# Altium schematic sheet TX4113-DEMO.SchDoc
size A3; Author: 周跃鸿; CompanyName: 深圳市芯鼎盛技术有限公司; SheetNumber: A
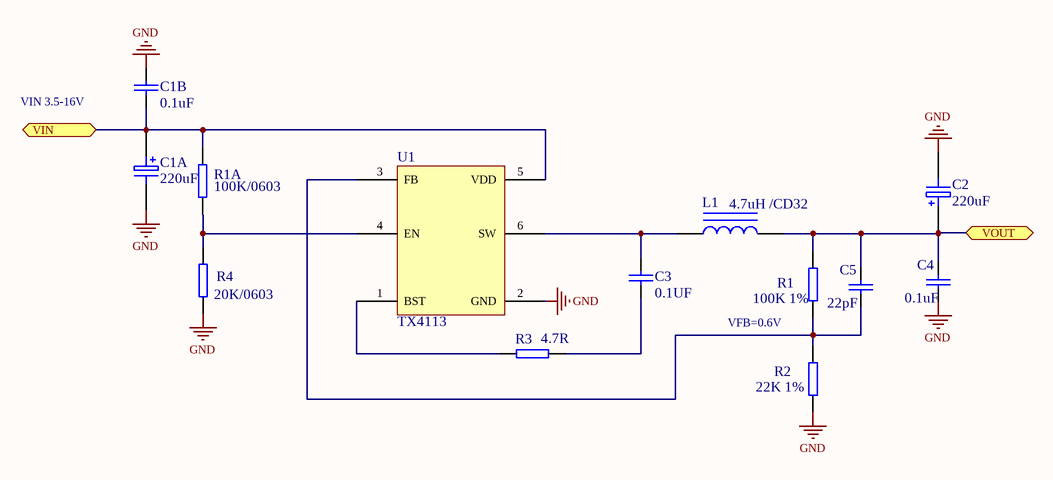
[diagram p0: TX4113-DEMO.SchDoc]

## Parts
C1A  220uF  [C10*16]
C1B  0.1uF  [C0805]
C2  220uF  [C10*16]
C3  0.1UF  [C0805]
C4  0.1uF  [C0805]
C5  22pF  [C0805]
L1  4.7uH /CD32  [L3015]
R1  100K 1%  [R0402]
R1A  100K/0603  [R0402]
R2  22K 1%  [R0402]
R3  4.7R  [R0402]
R4  20K/0603  [R0402]
U1  TX4113  [SOT23-6]

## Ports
VIN, VOUT (bidir)

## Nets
GND: C1A.2 C1B.1 C2.2 C4.2 R2.1 R4.1 U1.2(GND)
VIN: C1A.1 C1B.2 R1A.2 U1.5(VDD) ; port VIN
VOUT: C2.1 C4.1 C5.1 L1.2 R1.2 ; port VOUT
NetC3_1: C3.1 R3.1
NetC3_2: C3.2 L1.1 U1.6(SW)
NetC5_2: C5.2 R1.1 R2.2 U1.3(FB)
NetR1A_1: R1A.1 R4.2 U1.4(EN)
NetR3_2: R3.2 U1.1(BST)

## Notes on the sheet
- VIN 3.5-16V
- VFB=0.6V

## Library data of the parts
C1A C2 = ELECTRO1: Electrolytic Capacitor
C1B C3-C5 = CAP: Capacitor
L1 = L
R1 R1A R2-R4 = R: R?
U1 = TX4208D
